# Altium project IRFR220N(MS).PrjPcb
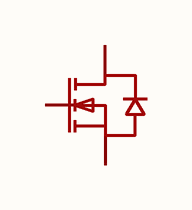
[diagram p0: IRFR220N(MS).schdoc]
1 sheet, 1 parts. Net scope: global (net labels, ports and power ports of the same name join across sheets).

## Sheet IRFR220N(MS).schdoc
size 127 x 101 mm

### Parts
Q?  irfr220n(ms)  [TO-252-2_L6.6-W6.1-P4.57-LS9.9-BR-CW]  (value not drawn)

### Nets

Not connected (* = marked no-connect by the designer): Q? 1(G) 2(D) 3(S)

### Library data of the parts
Q? = irfr220n(ms): 数量:1个N沟道;漏源电压(Vdss):200V;连续漏极电流(Id):8A;导通电阻(RDS(on)):300mΩ@10V;耗散功率(Pd):55W;阈值电压(Vgs(th)):2.5V;; Manufacturer: MSKSEMI(美森科); AddInBom: yes; ModelId: ce57f84d66384067af8a68020b6de06d; ModelName: TO-252-2L-3P_L6.6-W6.1-H2.3-LS10.1-P4.6; ModelTransform: 259.842,390.52442,0,90,0,0,-39.39,0,0; Number: 1个N沟道; Drain to Source Voltage: 200V; Current - Continuous Drain(Id): 8A; Pd - Power Dissipation: 55W; Gate Threshold Voltage (Vgs(th)): 2.5V; Gate Charge(Qg): 16nC@10V; Input Capacitance(Ciss): 540pF; Reverse Transfer Capacitance (Crss@Vds): 35pF; Output Capacitance(Coss): 90pF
